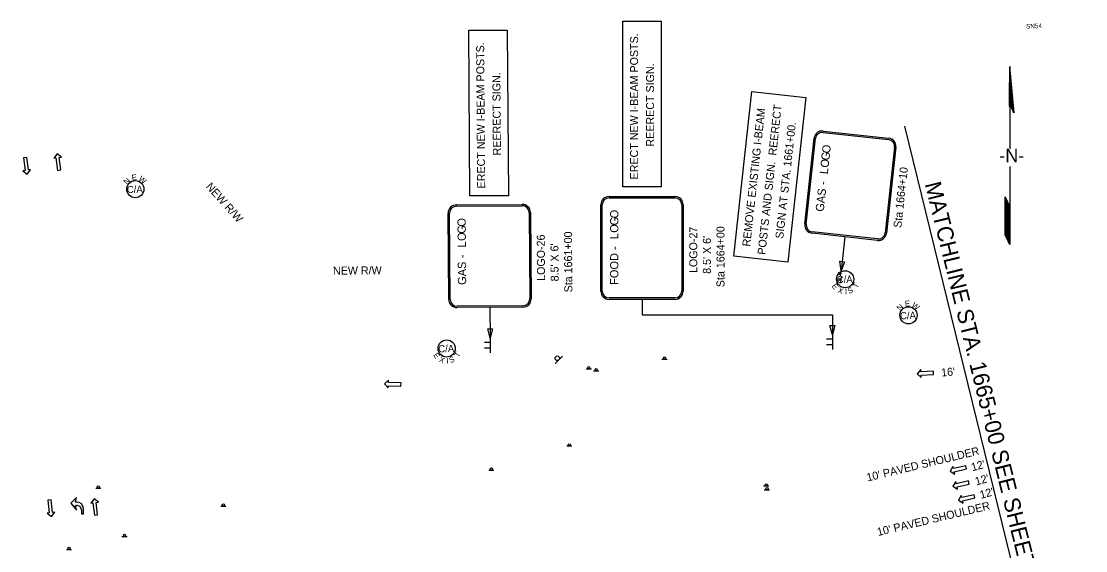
# Model space of a CAD drawing. Extents: x 1811940 to 1813538, y 1189643 to 1190703.
# Drawn here: x 1812607 to 1813538, y 1190240 to 1190703 of the extents above; entities that cross this region are included whole.
import ezdxf

# ---------------------------------------------------------------- set-up
doc = ezdxf.new("R2010")
doc.units = 0
for name, color, linetype in [('RD_PD_Final_LnLine', 7, 'Continuous'), ('RD_PD_Final_TX', 7, 'Continuous'), ('RD_PD_RW_TX', 7, 'Continuous'), ('RD_SHT_MatchLine', 7, 'Continuous'), ('RD_SHT_TX', 7, 'Continuous'), ('RD_Sketch1', 7, 'Continuous'), ('RD_Sketch10', 7, 'Continuous'), ('RD_Sketch8', 7, 'Continuous'), ('SN_P_Signs', 7, 'Continuous')]:
    doc.layers.add(name, color=color, linetype=linetype)

# ---------------------------------------------------------------- blocks, each defined once
blk = doc.blocks.new('SARRW2')
at = {"layer": 'RD_PD_Final_LnLine'}
blk.add_lwpolyline([(-12, 1.2), (-12, -1.2), (-2.83, -1.2), (-2.83, -2.83), (0, 0), (-2.83, 2.83), (-2.83, 1.2)], close=True, dxfattribs=at)

msp = doc.modelspace()

# ---------------------------------------------------------------- linework, layer by layer
at = {"layer": 'RD_PD_Final_LnLine'}
for p, q in [((1812655.24, 1190286.43), (1812650.32, 1190281.52)), ((1812655.24, 1190286.43), (1812650.32, 1190281.52)), ((1812654.3, 1190282.43), (1812655.24, 1190286.43)), ((1812654.3, 1190282.43), (1812655.24, 1190286.43)), ((1812650.32, 1190281.52), (1812655.15, 1190275.5)), ((1812650.32, 1190281.52), (1812655.15, 1190275.5)), ((1812655.38, 1190282.47), (1812654.3, 1190282.43)), ((1812655.38, 1190282.47), (1812654.3, 1190282.43)), ((1812654.4, 1190279.55), (1812655.48, 1190279.59)), ((1812654.4, 1190279.55), (1812655.48, 1190279.59)), ((1812655.15, 1190275.5), (1812654.4, 1190279.55)), ((1812655.15, 1190275.5), (1812654.4, 1190279.55)), ((1812659.58, 1190275.65), (1812659.71, 1190272.18)), ((1812659.58, 1190275.65), (1812659.71, 1190272.18)), ((1812661.51, 1190272.24), (1812661.34, 1190276.8)), ((1812661.51, 1190272.24), (1812661.34, 1190276.8)), ((1812659.71, 1190272.18), (1812661.51, 1190272.24)), ((1812659.71, 1190272.18), (1812661.51, 1190272.24)), ((1812659.71, 1190272.18), (1812659.71, 1190272.18)), ((1812659.71, 1190272.18), (1812659.71, 1190272.18))]:
    msp.add_line(p, q, dxfattribs=at)
for centre, radius, start, end in [((1812655.47, 1190276.59), 5.88, 2.00645, 90.849), ((1812655.47, 1190276.59), 5.88, 2.00645, 90.849), ((1812655.62, 1190275.64), 3.96, 0.28187, 92.04469), ((1812655.62, 1190275.64), 3.96, 0.28187, 92.04469)]:
    msp.add_arc(centre, radius, start, end, dxfattribs=at)
at = {"layer": 'RD_SHT_MatchLine'}
msp.add_line((1813379.72, 1190611.46), (1813538.24, 1189965.46), dxfattribs=at)
at = {"layer": 'RD_Sketch1'}
for p, q in [((1813471.78, 1190663.94), (1813471.57, 1190628.78)), ((1813475.5, 1190623.24), (1813471.78, 1190663.94)), ((1813471.78, 1190629.07), (1813471.78, 1190607.25)), ((1813472.08, 1190630.18), (1813475.5, 1190623.24)), ((1813471.78, 1190607.25), (1813471.78, 1190591.78)), ((1813471.78, 1190576.33), (1813471.78, 1190550.56)), ((1813467.78, 1190535.5), (1813467.78, 1190549.67)), ((1813467.78, 1190549.67), (1813471.78, 1190541.11)), ((1813471.78, 1190550.56), (1813471.78, 1190508.04)), ((1813467.78, 1190516.6), (1813467.78, 1190535.5)), ((1813471.78, 1190508.04), (1813467.78, 1190516.6))]:
    msp.add_line(p, q, dxfattribs=at)
for points in [[(1813471.79, 1190629.38), (1813471.79, 1190663.82)], [(1813471.88, 1190629.64), (1813471.88, 1190662.79)], [(1813471.98, 1190629.9), (1813471.98, 1190661.76)], [(1813472.07, 1190630.16), (1813472.07, 1190660.72)], [(1813472.17, 1190630.01), (1813472.17, 1190659.69)], [(1813472.26, 1190629.82), (1813472.26, 1190658.66)], [(1813472.36, 1190629.62), (1813472.36, 1190657.63)], [(1813472.45, 1190629.43), (1813472.45, 1190656.59)], [(1813471.69, 1190629.12), (1813471.69, 1190649.9)], [(1813472.54, 1190629.24), (1813472.54, 1190655.56)], [(1813472.64, 1190629.05), (1813472.64, 1190654.53)], [(1813472.73, 1190628.86), (1813472.73, 1190653.5)], [(1813472.83, 1190628.66), (1813472.83, 1190652.46)], [(1813472.92, 1190628.47), (1813472.92, 1190651.43)], [(1813473.02, 1190628.28), (1813473.02, 1190650.4)], [(1813473.11, 1190628.09), (1813473.11, 1190649.37)], [(1813473.21, 1190627.9), (1813473.21, 1190648.33)], [(1813473.3, 1190627.71), (1813473.3, 1190647.3)], [(1813473.4, 1190627.51), (1813473.4, 1190646.27)], [(1813473.49, 1190627.32), (1813473.49, 1190645.24)], [(1813473.58, 1190627.13), (1813473.58, 1190644.2)], [(1813473.68, 1190626.94), (1813473.68, 1190643.17)], [(1813473.77, 1190626.75), (1813473.77, 1190642.14)], [(1813473.87, 1190626.56), (1813473.87, 1190641.11)], [(1813473.96, 1190626.36), (1813473.96, 1190640.07)], [(1813474.06, 1190626.17), (1813474.06, 1190639.04)], [(1813474.15, 1190625.98), (1813474.15, 1190638.01)], [(1813471.6, 1190628.86), (1813471.6, 1190634)], [(1813474.25, 1190625.79), (1813474.25, 1190636.98)], [(1813474.34, 1190625.6), (1813474.34, 1190635.94)], [(1813474.43, 1190625.41), (1813474.43, 1190634.91)], [(1813474.53, 1190625.21), (1813474.53, 1190633.88)], [(1813474.62, 1190625.02), (1813474.62, 1190632.85)], [(1813474.72, 1190624.83), (1813474.72, 1190631.81)], [(1813474.81, 1190624.64), (1813474.81, 1190630.78)], [(1813474.91, 1190624.45), (1813474.91, 1190629.75)], [(1813475, 1190624.26), (1813475, 1190628.72)], [(1813475.1, 1190624.06), (1813475.1, 1190627.68)], [(1813475.19, 1190623.87), (1813475.19, 1190626.65)], [(1813475.29, 1190623.68), (1813475.29, 1190625.62)], [(1813475.38, 1190623.49), (1813475.38, 1190624.58)], [(1813475.47, 1190623.3), (1813475.47, 1190623.55)], [(1813467.86, 1190516.43), (1813467.86, 1190549.51)], [(1813467.96, 1190516.23), (1813467.96, 1190549.3)], [(1813468.05, 1190516.03), (1813468.05, 1190549.1)], [(1813468.14, 1190515.83), (1813468.14, 1190548.9)], [(1813468.24, 1190515.62), (1813468.24, 1190548.69)], [(1813468.33, 1190515.42), (1813468.33, 1190548.49)], [(1813468.43, 1190515.22), (1813468.43, 1190548.29)], [(1813468.52, 1190515.02), (1813468.52, 1190548.09)], [(1813468.62, 1190514.81), (1813468.62, 1190547.88)], [(1813468.71, 1190514.61), (1813468.71, 1190547.68)], [(1813468.81, 1190514.41), (1813468.81, 1190547.48)], [(1813468.9, 1190514.21), (1813468.9, 1190547.28)], [(1813469, 1190514), (1813469, 1190547.07)], [(1813469.09, 1190513.8), (1813469.09, 1190546.87)], [(1813469.18, 1190513.6), (1813469.18, 1190546.67)], [(1813469.28, 1190513.4), (1813469.28, 1190546.47)], [(1813469.37, 1190513.19), (1813469.37, 1190546.26)], [(1813469.47, 1190512.99), (1813469.47, 1190546.06)], [(1813469.56, 1190512.79), (1813469.56, 1190545.86)], [(1813469.66, 1190512.58), (1813469.66, 1190545.66)], [(1813469.75, 1190512.38), (1813469.75, 1190545.45)], [(1813469.85, 1190512.18), (1813469.85, 1190545.25)], [(1813469.94, 1190511.98), (1813469.94, 1190545.05)], [(1813470.03, 1190511.77), (1813470.03, 1190544.84)], [(1813470.13, 1190511.57), (1813470.13, 1190544.64)], [(1813470.22, 1190511.37), (1813470.22, 1190544.44)], [(1813470.32, 1190511.17), (1813470.32, 1190544.24)], [(1813470.41, 1190510.96), (1813470.41, 1190544.03)], [(1813470.51, 1190510.76), (1813470.51, 1190543.83)], [(1813470.6, 1190510.56), (1813470.6, 1190543.63)], [(1813470.7, 1190510.36), (1813470.7, 1190543.43)], [(1813470.79, 1190510.15), (1813470.79, 1190543.22)], [(1813470.89, 1190509.95), (1813470.89, 1190543.02)], [(1813470.98, 1190509.75), (1813470.98, 1190542.82)], [(1813471.07, 1190509.55), (1813471.07, 1190542.62)], [(1813471.17, 1190509.34), (1813471.17, 1190542.41)], [(1813471.26, 1190509.14), (1813471.26, 1190542.21)], [(1813471.36, 1190508.94), (1813471.36, 1190542.01)], [(1813471.45, 1190508.73), (1813471.45, 1190541.81)], [(1813471.55, 1190508.53), (1813471.55, 1190541.6)], [(1813471.64, 1190508.33), (1813471.64, 1190541.4)], [(1813471.74, 1190508.13), (1813471.74, 1190541.2)]]:
    msp.add_lwpolyline(points, dxfattribs=at)
at = {"layer": 'RD_Sketch10'}
for centre in [(1812706.7, 1190556.47), (1813383.16, 1190446)]:
    msp.add_circle(centre, 7.5, dxfattribs=at)
at = {"layer": 'RD_Sketch8'}
for centre in [(1813327.79, 1190477.56), (1812979.18, 1190416.99)]:
    msp.add_circle(centre, 7.5, dxfattribs=at)
at = {"layer": 'SN_P_Signs'}
for p, q in [((1813133.24, 1190558.42), (1813133.24, 1190703.44)), ((1813133.24, 1190703.44), (1813166.86, 1190703.44)), ((1813166.86, 1190703.44), (1813166.86, 1190558.42)), ((1812998.48, 1190695.51), (1813032.1, 1190695.75)), ((1812999.53, 1190550.49), (1812998.48, 1190695.51)), ((1813032.1, 1190695.75), (1813033.14, 1190550.73)), ((1813230.32, 1190497.72), (1813246.1, 1190641.88)), ((1813246.1, 1190641.88), (1813293.44, 1190636.7)), ((1813293.44, 1190636.7), (1813277.66, 1190492.54)), ((1813166.86, 1190558.42), (1813133.24, 1190558.42)), ((1813033.14, 1190550.73), (1812999.53, 1190550.49)), ((1813327.42, 1190514.76), (1813324.15, 1190484.95)), ((1813277.66, 1190492.54), (1813230.32, 1190497.72)), ((1813323.66, 1190480.48), (1813324.15, 1190484.95)), ((1813324.13, 1190475.02), (1813324.62, 1190479.49)), ((1813017.04, 1190452.94), (1813017.23, 1190426.08)), ((1813150.05, 1190459.98), (1813150.05, 1190446.3)), ((1813150.05, 1190446.3), (1813316.56, 1190446.3)), ((1813316.56, 1190446.3), (1813316.56, 1190428.99)), ((1813017.23, 1190426.08), (1813017.33, 1190413.04)), ((1813316.56, 1190425.08), (1813311.57, 1190425.08)), ((1813316.56, 1190428.99), (1813316.56, 1190415.95)), ((1813017.26, 1190422.17), (1813012.27, 1190422.14)), ((1813017.3, 1190417.16), (1813012.31, 1190417.12)), ((1813316.56, 1190420.06), (1813311.57, 1190420.06)), ((1813074.19, 1190403.76), (1813080.56, 1190410.12)), ((1813167.44, 1190407.5), (1813171.94, 1190407.5)), ((1813101.21, 1190399.03), (1813105.71, 1190399.03)), ((1813107.67, 1190397.49), (1813112.17, 1190397.49)), ((1813084.19, 1190331.61), (1813088.69, 1190331.61)), ((1813015.99, 1190310.32), (1813020.49, 1190310.32)), ((1812672.09, 1190294.69), (1812676.59, 1190294.69)), ((1813256.46, 1190296.59), (1813260.96, 1190296.59)), ((1813257.04, 1190293.16), (1813261.54, 1190293.16)), ((1812781.51, 1190278.97), (1812786.01, 1190278.97)), ((1812695.03, 1190252.34), (1812699.53, 1190252.34)), ((1812646.44, 1190240.99), (1812650.94, 1190240.99))]:
    msp.add_line(p, q, dxfattribs=at)
for points in [[(1813292.41, 1190525.84), (1813300.64, 1190600.99)], [(1813293.61, 1190525.71), (1813301.84, 1190600.86)], [(1813308.45, 1190606.17), (1813365.71, 1190599.9)], [(1813308.58, 1190607.36), (1813365.84, 1190601.09)], [(1813371.02, 1190593.28), (1813362.79, 1190518.13)], [(1813372.21, 1190593.15), (1813363.99, 1190518)], [(1813121.25, 1190549.98), (1813178.85, 1190549.98)], [(1813121.25, 1190548.78), (1813178.85, 1190548.78)], [(1812980.99, 1190459.88), (1812980.44, 1190535.48)], [(1812982.19, 1190459.89), (1812981.64, 1190535.49)], [(1812987.59, 1190542.73), (1813045.19, 1190543.15)], [(1812987.6, 1190541.53), (1813045.2, 1190541.95)], [(1813051.24, 1190535.99), (1813051.79, 1190460.4)], [(1813052.44, 1190536), (1813052.99, 1190460.4)], [(1813114.05, 1190467.18), (1813114.05, 1190542.78)], [(1813115.25, 1190467.18), (1813115.25, 1190542.78)], [(1813184.85, 1190542.78), (1813184.85, 1190467.18)], [(1813186.05, 1190542.78), (1813186.05, 1190467.18)], [(1813356.05, 1190511.63), (1813298.79, 1190517.9)], [(1813356.18, 1190512.82), (1813298.92, 1190519.09)], [(1813178.85, 1190461.18), (1813121.25, 1190461.18)], [(1813045.83, 1190454.35), (1812988.23, 1190453.94)], [(1813045.84, 1190453.15), (1812988.24, 1190452.74)], [(1813178.85, 1190459.98), (1813121.25, 1190459.98)]]:
    msp.add_lwpolyline(points, dxfattribs=at)
for points in [[(1813327.09, 1190492.88), (1813324.15, 1190484.95), (1813323.01, 1190493.33)], [(1813019.22, 1190434.3), (1813017.23, 1190426.08), (1813015.12, 1190434.27)], [(1813318.61, 1190437.19), (1813316.56, 1190428.99), (1813314.51, 1190437.19)]]:
    msp.add_lwpolyline(points, close=True, dxfattribs=at)
for centre, radius in [((1813322.9, 1190482.84), 1), ((1813323.37, 1190477.37), 1), ((1813075.95, 1190408.38), 2), ((1813169.7, 1190408.51), 1), ((1813103.47, 1190400.04), 1), ((1813109.93, 1190398.5), 1), ((1813086.45, 1190332.62), 1), ((1813018.25, 1190311.34), 1), ((1812674.34, 1190295.71), 1), ((1813258.71, 1190297.6), 1), ((1813259.3, 1190294.17), 1), ((1812783.77, 1190279.98), 1), ((1812697.29, 1190253.35), 1), ((1812648.69, 1190242), 1)]:
    msp.add_circle(centre, radius, dxfattribs=at)
for centre, radius, start, end in [((1813307.8, 1190600.21), 7.2, 83.75218, 173.75218), ((1813307.8, 1190600.21), 6, 83.75218, 173.75218), ((1813365.06, 1190593.94), 6, 353.75218, 83.75218), ((1813365.06, 1190593.94), 7.2, 353.75218, 83.75218), ((1813121.25, 1190542.78), 7.2, 90, 180), ((1813121.25, 1190542.78), 6, 90, 180), ((1813178.85, 1190542.78), 7.2, 0, 90), ((1813178.85, 1190542.78), 6, 0, 90), ((1812987.64, 1190535.53), 7.2, 90.41339, 180.41339), ((1812987.64, 1190535.53), 6, 90.41339, 180.41339), ((1813045.24, 1190535.95), 7.2, 0.41339, 90.41339), ((1813045.24, 1190535.95), 6, 0.41339, 90.41339), ((1813299.57, 1190525.05), 7.2, 173.75218, 263.75218), ((1813299.57, 1190525.05), 6, 173.75218, 263.75218), ((1813356.83, 1190518.79), 7.2, 263.75218, 353.75218), ((1813356.83, 1190518.79), 6, 263.75218, 353.75218), ((1813045.79, 1190460.35), 6, 270.41339, 0.41339), ((1813045.79, 1190460.35), 7.2, 270.41339, 0.41339), ((1813121.25, 1190467.18), 7.2, 180, 270), ((1813121.25, 1190467.18), 6, 180, 270), ((1813178.85, 1190467.18), 6, 270, 0), ((1813178.85, 1190467.18), 7.2, 270, 0), ((1812988.19, 1190459.94), 7.2, 180.41339, 270.41339), ((1812988.19, 1190459.94), 6, 180.41339, 270.41339)]:
    msp.add_arc(centre, radius, start, end, dxfattribs=at)

# ---------------------------------------------------------------- block references
at = {"layer": 'RD_PD_Final_LnLine'}
for p, xscale, yscale, rotation in [((1812612.15, 1190569.69), 1.2000000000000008, 1.2000000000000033, -82.77626835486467), ((1812638.29, 1190587.34), 1.2000000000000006, 1.2000000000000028, 97.22373164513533), ((1813390.73, 1190394.81), 1.1999999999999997, 1.2, -176.2603687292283), ((1812924.74, 1190385.92), 1.1999999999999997, 1.2000000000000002, 177.7114801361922), ((1813419.55, 1190309.56), 1.1999999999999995, 1.2000000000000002, -166.51198634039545), ((1813422.02, 1190296.3), 1.1999999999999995, 1.2000000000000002, -166.51198634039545), ((1812633.28, 1190269.89), 1.2000000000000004, 1.2000000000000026, -83.3603928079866), ((1812670.67, 1190285.43), 1.2000000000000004, 1.2000000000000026, 96.63960719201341), ((1813426.88, 1190284.18), 1.1999999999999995, 1.2000000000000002, -166.51198634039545)]:
    msp.add_blockref('SARRW2', p, dxfattribs=dict(at, xscale=xscale, yscale=yscale, rotation=rotation))

# ---------------------------------------------------------------- texts
at = {"layer": 'RD_PD_Final_TX'}
for s, rotation, p in [("16'", 5.04887, (1813412.03, 1190392.37)), ("10' PAVED SHOULDER", 13.57482, (1813347.39, 1190300.47)), ("12'", 15.26767, (1813439.07, 1190309.4)), ("12'", 15.26767, (1813442.48, 1190297.03)), ("12'", 15.26767, (1813446.58, 1190285.29)), ("10' PAVED SHOULDER", 13.40417, (1813356.63, 1190252.74))]:
    msp.add_text(s, height=7, rotation=rotation, dxfattribs=at).set_placement(p)
at = {"layer": 'RD_PD_RW_TX'}
for rotation, p in [(311.76828, (1812768, 1190558.35)), (0.41339, (1812879.69, 1190481.61))]:
    msp.add_text('NEW R/W', height=7, rotation=rotation, dxfattribs=at).set_placement(p)
at = {"layer": 'RD_SHT_TX'}
for s, height, rotation, p in [('SN54', 4, 2.01838, (1813486.18, 1190697.04)), ('MATCHLINE STA. 1665+00 SEE SHEET NO. SN55', 14.1726, 283.90674, (1813397.34, 1190561.08))]:
    msp.add_text(s, height=height, rotation=rotation, dxfattribs=at).set_placement(p)
at = {"layer": 'RD_Sketch1'}
msp.add_text('-N-', height=11.811, rotation=0, dxfattribs=at).set_placement((1813462.58, 1190580.04))
at = {"layer": 'RD_Sketch10'}
for s, height, rotation, p in [('N', 5, 46.88815, (1812699.45, 1190560.05)), ('E', 5, 6.35143, (1812703.87, 1190564.08)), ('W', 5, 321.321, (1812709.04, 1190564.51)), ('C/A', 6.25, 2.01838, (1812699.41, 1190552.93)), ('N', 5, 46.88815, (1813375.91, 1190449.59)), ('E', 5, 6.35143, (1813380.33, 1190453.61)), ('W', 5, 321.321, (1813385.5, 1190454.05)), ('C/A', 6.25, 2.01838, (1813375.87, 1190442.47))]:
    msp.add_text(s, height=height, rotation=rotation, dxfattribs=at).set_placement(p)
at = {"layer": 'RD_Sketch8'}
for s, height, rotation, p in [('C/A', 6.25, 2.01838, (1813320.49, 1190474.02)), ('E', 5, 305.22963, (1813315.77, 1190471.61)), ('X', 5, 337.659, (1813320.74, 1190466.13)), ('S', 5, 23.81082, (1813331.24, 1190464.6)), ('T', 5, 60.20353, (1813338.28, 1190469.21)), ('I', 5, 1.819, (1813327.59, 1190464.3)), ('C/A', 6.25, 2.01838, (1812971.89, 1190413.45)), ('T', 5, 60.20353, (1812989.67, 1190408.64)), ('E', 5, 305.22963, (1812967.16, 1190411.04)), ('X', 5, 337.659, (1812972.14, 1190405.56)), ('I', 5, 1.819, (1812978.99, 1190403.72)), ('S', 5, 23.81082, (1812982.63, 1190404.03))]:
    msp.add_text(s, height=height, rotation=rotation, dxfattribs=at).set_placement(p)
at = {"layer": 'SN_P_Signs'}
for s, height, rotation, p in [('ERECT NEW I-BEAM POSTS.', 6.9998, 90.41347, (1813012.84, 1190557.13)), ('ERECT NEW I-BEAM POSTS.', 6.9998, 90.00008, (1813146.6, 1190564.96)), ('REERECT SIGN.', 6.9998, 90.00008, (1813160.6, 1190593.76)), ('REERECT SIGN.', 6.9998, 90.41347, (1813026.63, 1190586.03)), ('POSTS AND SIGN.  REERECT', 6.9998, 83.75226, (1813257.96, 1190498.75)), ('REMOVE EXISTING I-BEAM', 6.9998, 83.75226, (1813244.66, 1190505.95)), ('SIGN AT STA. 1661+00.', 6.9998, 83.75226, (1813273.58, 1190512.82)), ('O', 7.2, 83.75218, (1813314.56, 1190587.5)), ('O', 7.2, 83.75218, (1813314.56, 1190587.5)), ('O', 7.2, 83.75218, (1813313.19, 1190574.98)), ('O', 7.2, 83.75218, (1813313.19, 1190574.98)), ('G', 7.2, 83.75218, (1813313.88, 1190581.35)), ('G', 7.2, 83.75218, (1813313.88, 1190581.35)), ('L', 7.2, 83.75218, (1813312.56, 1190569.27)), ('L', 7.2, 83.75218, (1813312.56, 1190569.27)), ('Sta 1664+10', 7, 83.75226, (1813376.91, 1190522.33)), ('-', 7.2, 83.75218, (1813311.54, 1190559.96)), ('-', 7.2, 83.75218, (1813311.54, 1190559.96)), ('GAS', 7.2, 83.75218, (1813308.97, 1190536.46)), ('O', 7.2, 90, (1813129.35, 1190530.88)), ('O', 7.2, 90, (1813129.35, 1190530.88)), ('O', 7.2, 90.41339, (1812995.83, 1190523.7)), ('O', 7.2, 90.41339, (1812995.83, 1190523.7)), ('G', 7.2, 90, (1813129.35, 1190524.7)), ('G', 7.2, 90, (1813129.35, 1190524.7)), ('O', 7.2, 90, (1813129.35, 1190518.28)), ('O', 7.2, 90, (1813129.35, 1190518.28)), ('G', 7.2, 90.41339, (1812995.87, 1190517.51)), ('G', 7.2, 90.41339, (1812995.87, 1190517.51)), ('O', 7.2, 90.41339, (1812995.92, 1190511.1)), ('O', 7.2, 90.41339, (1812995.92, 1190511.1)), ('LOGO-26', 7, 90.41347, (1813065.24, 1190476.18)), ('Sta 1661+00', 7, 90.41347, (1813089.12, 1190466.1)), ('L', 7.2, 90, (1813129.35, 1190512.55)), ('L', 7.2, 90, (1813129.35, 1190512.55)), ('LOGO-27', 7, 90.00008, (1813198.42, 1190483.03)), ('Sta 1664+00', 7, 90.00008, (1813222.22, 1190470.63)), ('L', 7.2, 90.41339, (1812995.96, 1190505.36)), ('L', 7.2, 90.41339, (1812995.96, 1190505.36)), ("8.5' X 6'", 7, 90.41347, (1813077.15, 1190475.72)), ("8.5' X 6'", 7, 90.00008, (1813210.32, 1190482.31)), ('-', 7.2, 90.41339, (1812996.03, 1190495.99)), ('-', 7.2, 90.41339, (1812996.03, 1190495.99)), ('FOOD', 7.2, 90, (1813129.35, 1190472.67)), ('-', 7.2, 90, (1813129.35, 1190503.18)), ('-', 7.2, 90, (1813129.35, 1190503.18)), ('GAS', 7.2, 90.41339, (1812996.2, 1190472.67))]:
    msp.add_text(s, height=height, rotation=rotation, dxfattribs=at).set_placement(p)

doc.saveas('drawing.dxf')
